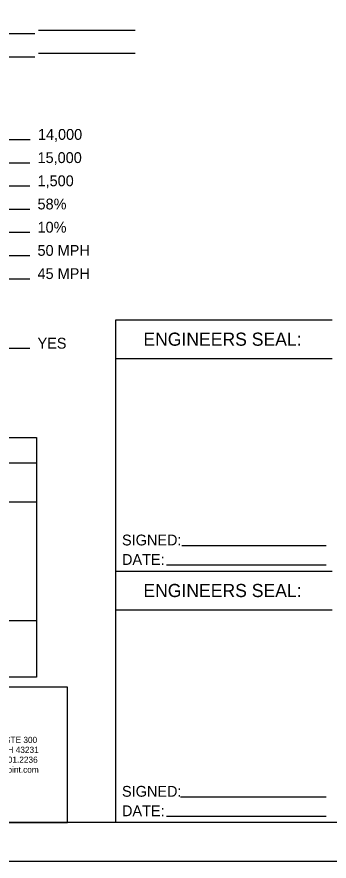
# Model space of a CAD drawing. Extents: x 10.6 to 44.6, y -2.6 to 23.4.
# Drawn here: x 18.57 to 22.61, y 1.43 to 12.34 of the extents above; entities that cross this region are included whole.
import ezdxf

# ---------------------------------------------------------------- set-up
doc = ezdxf.new("R2010")
doc.units = 0
for name, color, linetype in [('SH_Border', 7, 'Continuous'), ('SH_Cut_Line', 7, 'Continuous'), ('SH_Data', 7, 'Continuous')]:
    doc.layers.add(name, color=color, linetype=linetype)

msp = doc.modelspace()

# ---------------------------------------------------------------- linework, layer by layer
at = {"layer": 'SH_Border'}
msp.add_lwpolyline([(12.603, 22.926), (44.103, 22.926), (44.103, 1.926), (12.603, 1.926)], close=True, dxfattribs=at)
at = {"layer": 'SH_Cut_Line'}
msp.add_lwpolyline([(10.603, 1.426), (44.603, 1.426), (44.603, 23.426), (10.603, 23.426)], close=True, dxfattribs=at)
at = {"layer": 'SH_Data'}
for p, q in [((18.803, 12.124), (16.027, 12.124)), ((20.103, 12.17), (18.853, 12.17)), ((18.803, 11.824), (14.538, 11.824)), ((20.103, 11.87), (18.853, 11.87)), ((18.745, 10.754), (15.176, 10.754)), ((18.74, 10.454), (15.602, 10.454)), ((18.74, 10.154), (16.279, 10.154)), ((18.74, 9.854), (15.974, 9.854)), ((18.74, 9.554), (15.477, 9.554)), ((18.74, 9.254), (14.544, 9.254)), ((18.74, 8.954), (14.454, 8.954)), ((19.853, 5.176), (19.853, 8.426)), ((19.853, 8.426), (22.653, 8.426)), ((18.74, 8.054), (14.514, 8.054)), ((19.853, 7.926), (22.653, 7.926)), ((13.628, 6.579), (18.828, 6.579)), ((13.628, 6.073), (18.828, 6.073)), ((20.707, 5.509), (22.574, 5.509)), ((20.51, 5.257), (22.574, 5.257)), ((19.853, 1.926), (19.853, 5.176)), ((19.853, 5.176), (22.653, 5.176)), ((19.853, 4.676), (22.653, 4.676)), ((13.628, 4.539), (18.828, 4.539)), ((20.689, 2.259), (22.574, 2.259)), ((20.51, 2.007), (22.574, 2.007))]:
    msp.add_line(p, q, dxfattribs=at)
for points in [[(13.628, 6.904), (18.828, 6.904), (18.828, 3.804), (13.628, 3.804)], [(13.628, 6.904), (18.828, 6.904), (18.828, 3.804), (13.628, 3.804)], [(13.228, 1.926), (19.228, 1.926), (19.228, 3.676), (13.228, 3.676)]]:
    msp.add_lwpolyline(points, close=True, dxfattribs=at)

# ---------------------------------------------------------------- texts
for s, height, p in [('14,000', 0.14, (18.845, 10.754)), ('15,000', 0.14, (18.84, 10.454)), ('1,500', 0.14, (18.84, 10.154)), ('58%', 0.14, (18.84, 9.854)), ('10%', 0.14, (18.84, 9.554)), ('50 MPH', 0.14, (18.84, 9.254)), ('45 MPH', 0.14, (18.84, 8.954)), ('YES', 0.14, (18.84, 8.054)), ('ENGINEERS SEAL:', 0.17, (20.21, 8.091)), ('SIGNED:', 0.14, (19.933, 5.509)), ('DATE:', 0.14, (19.933, 5.257)), ('ENGINEERS SEAL:', 0.17, (20.21, 4.841)), ('2550 CORPORATE EXCHANGE DR, STE 300', 0.08, (16.6, 2.954)), ('COLUMBUS, OH 43231', 0.08, (17.702, 2.826)), ('TEL 614.901.2235   FAX 614.901.2236', 0.08, (16.98, 2.698)), ('www.structurepoint.com', 0.08, (17.714, 2.57)), ('SIGNED:', 0.14, (19.933, 2.259)), ('DATE:', 0.14, (19.933, 2.007))]:
    msp.add_text(s, height=height, dxfattribs=at).set_placement(p)

doc.saveas('drawing.dxf')
